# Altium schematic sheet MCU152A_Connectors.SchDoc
size 431 x 279 mm; Date: Not shown in title block; ApprovedBy: Not shown in title block; CheckedBy: Not shown in title block; Author: Not shown in title block; CompanyName: Not shown in title block; Engineer: Not shown in title block; Organization: Not shown in title block; Address1: Not shown in title block; Address2: Not shown in title block; Address3: Not shown in title block; Address4: Not shown in title block; DocumentNumber: 2; Revision: Use project parameter SCH_Rev; SheetNumber: 2; SheetTotal: 8; PageSetup: Record=PageOptions¦CenterHorizontal=True¦CenterVertical=True¦PrintScale=1.00¦XCorrection=1.00¦YCorrection=1.00¦PrintKind=0¦BorderSize=5000000¦LeftOffset=0¦BottomOffset=0¦Orientation=2¦PaperLength=1000¦PaperWidth=1000¦Scale=100¦PaperSource=15¦PrintQuality=600¦MediaType=1¦DitherType=10¦PaperKind=Letter¦PrintScaleMode=1
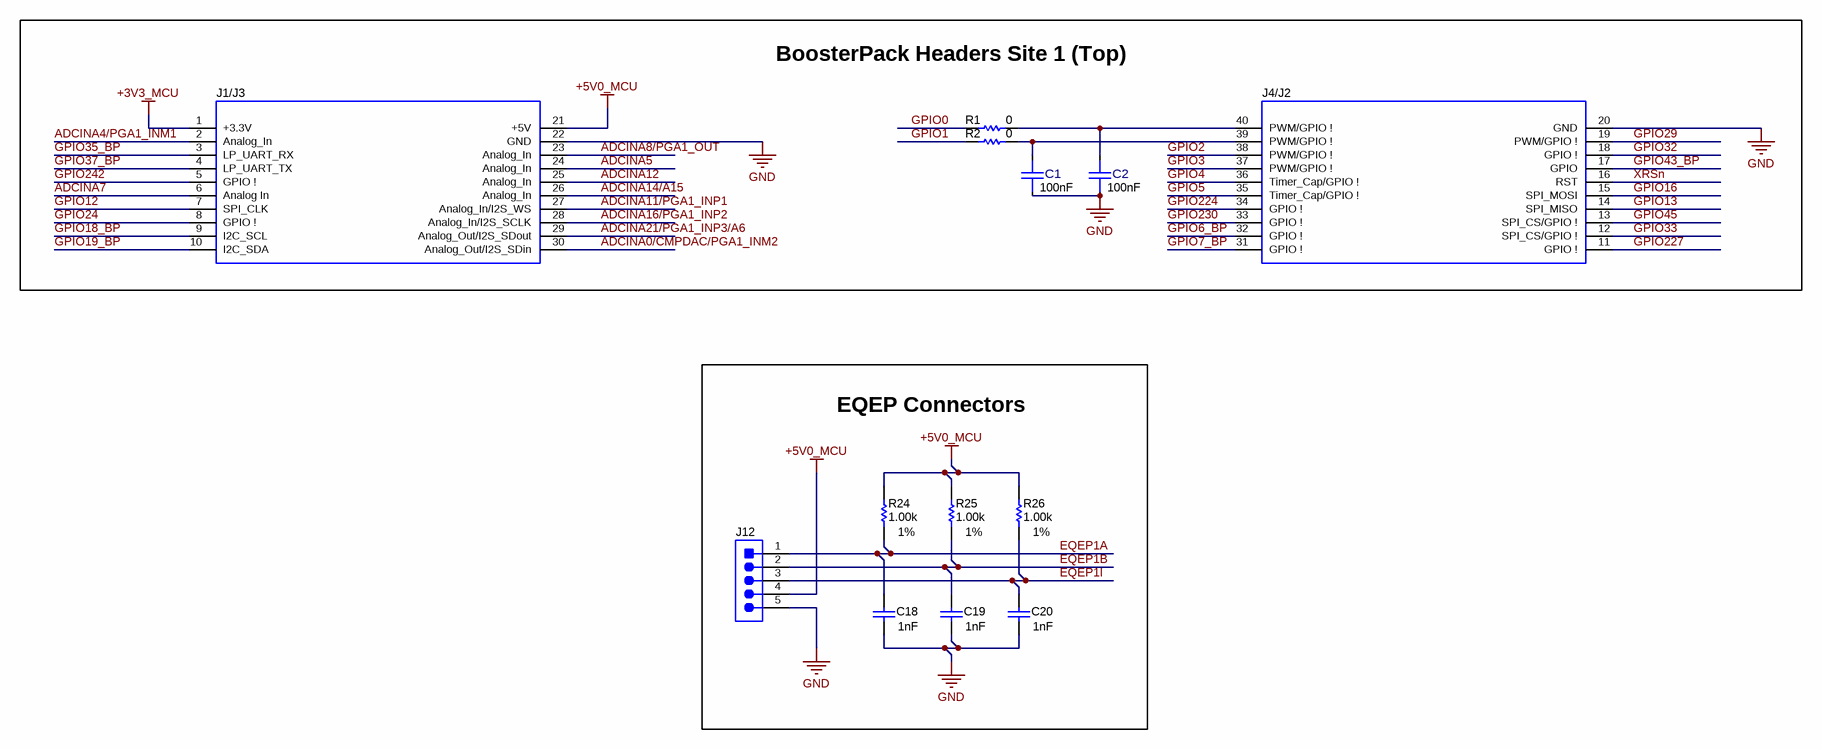
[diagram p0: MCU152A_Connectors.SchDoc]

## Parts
C1  Cap_F: 100nF  [FP-885012205018_0402-MFG]  (hidden comment: 885012205018)
C2  Cap_F: 100nF  [FP-885012205018_0402-MFG]  (hidden comment: 885012205018)
C18  Cap_F: 1nF  [0402]  (hidden comment: 885012205061)
C19  Cap_F: 1nF  [0402]  (hidden comment: 885012205061)
C20  Cap_F: 1nF  [0402]  (hidden comment: 885012205061)
J1/J3  SSQ-110-03-T-D  [BoosterPack_40pin_J1J3]  (value not drawn)
J4/J2  SSQ-110-03-T-D  [BoosterPack_40pin_J2J4]  (value not drawn)
J12  61300511121  [Wurth_61300511121]  (value not drawn)
R1  ValueDisplayed: 0  [0402]  (hidden comment: RC0402JR-070RL)
R2  ValueDisplayed: 0  [0402]  (hidden comment: RC0402JR-070RL)
R24  ValueDisplayed: 1.00k  Value1: 1%  [0402]  (hidden comment: CRCW04021K00FKED)
R25  ValueDisplayed: 1.00k  Value1: 1%  [0402]  (hidden comment: CRCW04021K00FKED)
R26  ValueDisplayed: 1.00k  Value1: 1%  [0402]  (hidden comment: CRCW04021K00FKED)

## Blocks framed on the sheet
BoosterPack Headers Site 1 (Top): C1 C2 J1/J3 J4/J2 R1 R2
EQEP Connectors: C18-C20 J12 R24-R26

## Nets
+3V3_MCU: J1/J3.1(+3.3V)
+5V0_MCU: J1/J3.21(+5V) J12.4 R24.2 R25.2 R26.2
GND: C1.1 C2.1 C18.2 C19.2 C20.2 J1/J3.22(GND) J4/J2.20(GND) J12.5
ADCINA0/CMPDAC/PGA1_INM2: J1/J3.30(Analog_Out/I2S_SDin)
ADCINA4/PGA1_INM1: J1/J3.2(Analog_In)
ADCINA5: J1/J3.24(Analog_In)
ADCINA7: J1/J3.6(Analog_In)
ADCINA8/PGA1_OUT: J1/J3.23(Analog_In)
ADCINA11/PGA1_INP1: J1/J3.27(Analog_In/I2S_WS)
ADCINA12: J1/J3.25(Analog_In)
ADCINA14/A15: J1/J3.26(Analog_In)
ADCINA16/PGA1_INP2: J1/J3.28(Analog_In/I2S_SCLK)
ADCINA21/PGA1_INP3/A6: J1/J3.29(Analog_Out/I2S_SDout)
EQEP1A: C18.1 J12.1 R24.1
EQEP1B: C19.1 J12.2 R25.1
EQEP1I: C20.1 J12.3 R26.1
GPIO0: R1.1
GPIO1: R2.1
GPIO2: J4/J2.38(PWM/GPIO_!)
GPIO3: J4/J2.37(PWM/GPIO_!)
GPIO4: J4/J2.36(Timer_Cap/GPIO_!)
GPIO5: J4/J2.35(Timer_Cap/GPIO_!)
GPIO6_BP: J4/J2.32(GPIO_!)
GPIO7_BP: J4/J2.31(GPIO_!)
GPIO12: J1/J3.7(SPI_CLK)
GPIO13: J4/J2.14(SPI_MISO)
GPIO16: J4/J2.15(SPI_MOSI)
GPIO18_BP: J1/J3.9(I2C_SCL)
GPIO19_BP: J1/J3.10(I2C_SDA)
GPIO24: J1/J3.8(GPIO_!)
GPIO29: J4/J2.19(PWM/GPIO_!)
GPIO32: J4/J2.18(GPIO_!)
GPIO33: J4/J2.12(SPI_CS/GPIO_!)
GPIO35_BP: J1/J3.3(LP_UART_RX)
GPIO37_BP: J1/J3.4(LP_UART_TX)
GPIO43_BP: J4/J2.17(GPIO)
GPIO45: J4/J2.13(SPI_CS/GPIO_!)
GPIO224: J4/J2.34(GPIO_!)
GPIO227: J4/J2.11(GPIO_!)
GPIO230: J4/J2.33(GPIO_!)
GPIO242: J1/J3.5(GPIO_!)
XRSn: J4/J2.16(RST)
NetC1_2: C1.2 J4/J2.39(PWM/GPIO_!) R2.2
NetC2_2: C2.2 J4/J2.40(PWM/GPIO_!) R1.2

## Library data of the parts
C1 C2 = CMP-0090362-1: 0.1µF ±10% 10V Ceramic Capacitor X7R 0402 (1005 Metric); Manufacturer: Wurth Electronics; AEC Qualified: No; Value: 100nF; SizeZ_mm: 0.55mm; ValueDisplayed: 100000pF; TempCo: 15%
C18-C20 = CMP-0006231-2: CAP, CERM, 1000 pF, 50 V, +/- 10%, X7R, 0402; Manufacturer: Wurth Elektronik; Polarized: N; Value: 1000pF; U/M: EA; Value1: Unknown; VDC_V: 50V; TaMin_C: -55°C; TaMax_C: 125°C; SizeArea_mm2: 0.5; SizeAreaWB_mm2: 3; SizeX_mm: 1; SizeZ_mm: 0.6; AEC Category: Q200
J1/J3 = CMP-0003837-4: Receptacle, 2.54mm, 10x2, Tin, TH; Alternate PartNumber: CRD-081413-A-G; Manufacturer: Samtec; Alternate Manufacturer: Major League Electronics; Note: Booster Pack 40 pin J1 and J3; Green_Lifecycle: Active; Green_REACh: Incomplete
J4/J2 = CMP-0078266-4: Receptacle, 2.54mm, 10x2, Tin, TH; Alternate PartNumber: CRD-081413-A-G; Manufacturer: Samtec; Alternate Manufacturer: Major League Electronics; Note: Booster Pack 40 pin J2 and J4; Green_REACh: Incomplete; Green_Lifecycle: Active
J12 = CMP-0084909-1: Header, 2.54mm, 5x1, Gold, TH; Manufacturer: Wurth Elektronik; Pitch_mm: 2.54; Gender: Male; Row_Count: 1; Shrouded: N; Current_A: 3A; Voltage_V: 250V
R1 R2 = CMP-0027004-2: RES, 0, 5%, 0.063 W, 0402; Manufacturer: Yageo America; Power_W: 63mW; TempCo: 200 ppm/C; Value_Code: 0000; U/M: EA; Value: 0; EIA_Code: E24; SizeX_mm: 1; SizeY_mm: 0.5; SizeZ_mm: 0.6; Value2: 0.063W; VDC_V: 50V; AEC Category: Q200
R24-R26 = CMP-0026071-3: RES, 1.00 k, 1%, 0.063 W, AEC-Q200 Grade 0, 0402; Manufacturer: Vishay-Dale; Value: 1.00k; Res_ohm: 1k; Value_Code: 1k00; Power_W: 63mW; Value2: 0.063W; VDC_V: 50V; TempCo: 100 ppm/C; SizeArea_mm2: 0.5; SizeX_mm: 1; SizeZ_mm: 0.6; EIA_Code: E96; AEC Category: Q200; AEC Qualified: Y; AEC Grade: 0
